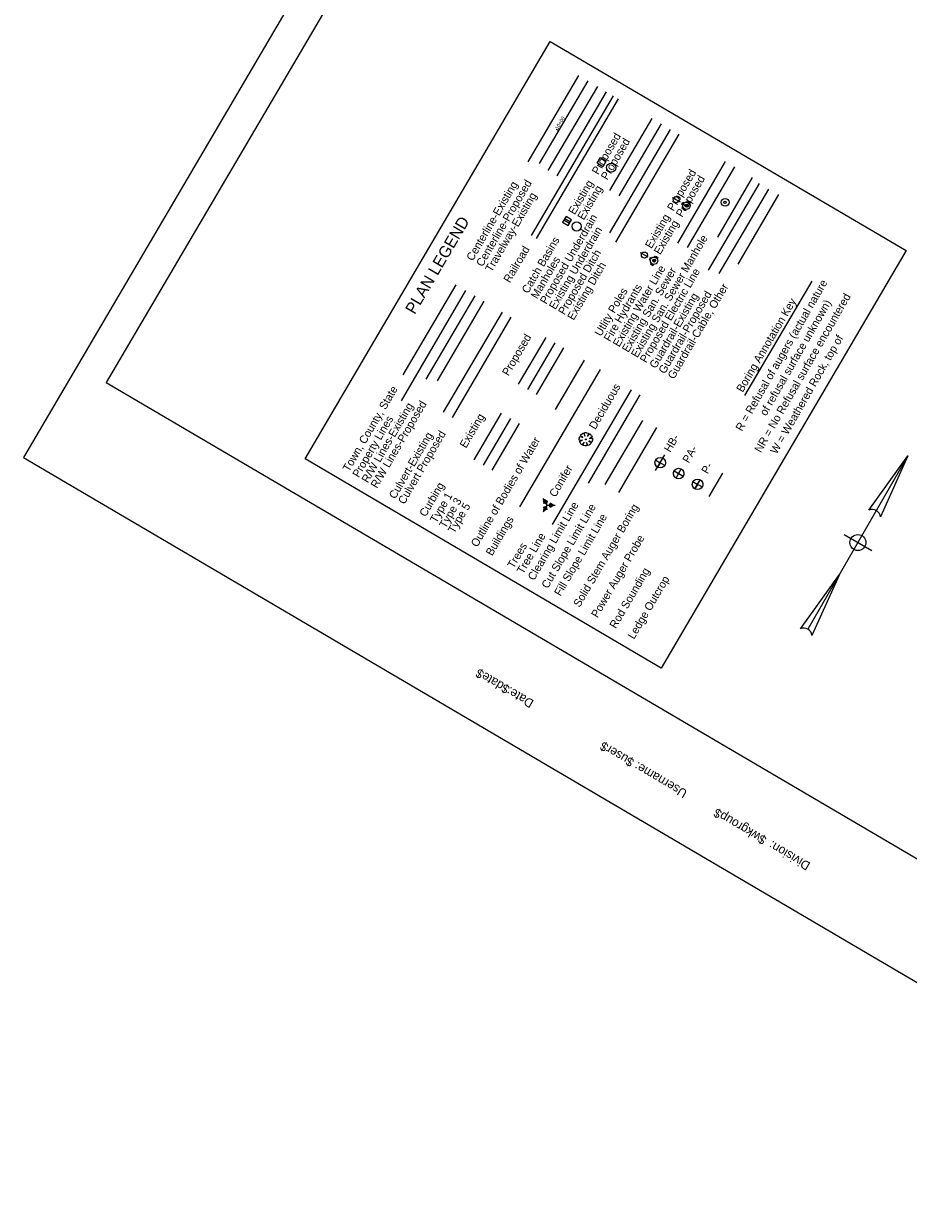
# Model space of a CAD drawing. Extents: x 423683 to 425040, y 89137 to 90655.
# Drawn here: x 423683 to 424180, y 89137 to 89799 of the extents above; entities that cross this region are included whole.
import ezdxf

# ---------------------------------------------------------------- set-up
doc = ezdxf.new("R2010")
doc.units = 0
for name, color, linetype in [('ANNOTATION', 7, 'Continuous'), ('BLDNGS_FEATS', 7, 'Continuous'), ('BORDER', 7, 'Continuous'), ('CENTERLINE', 7, 'Continuous'), ('CLOSED DRNAGE', 7, 'Continuous'), ('CRB_SDWK_RAIL', 7, 'Continuous'), ('Cross Line', 7, 'Continuous'), ('CUTFILLCLL', 7, 'Continuous'), ('Existing ROW', 7, 'Continuous'), ('H_V CONTROLS', 7, 'Continuous'), ('OPEN DRNAGE', 7, 'Continuous'), ('PCRB_PSW_PRAIL', 7, 'Continuous'), ('PDRAIN', 7, 'Continuous'), ('PLOT BOUNDARY', 7, 'Continuous'), ('PROP LINES', 7, 'Continuous'), ('PROPSD ROW LINES', 7, 'Continuous'), ('ROAD', 7, 'Continuous'), ('S_Utilities_UG_Electrical_Line', 7, 'Continuous'), ('State Seal', 7, 'Continuous'), ('TREES_BUSHES', 7, 'Continuous'), ('Truck Apron', 7, 'Continuous'), ('UTILS AERIAL', 7, 'Continuous'), ('UTILS GRND', 7, 'Continuous'), ('WATER_DAM', 7, 'Continuous')]:
    doc.layers.add(name, color=color, linetype=linetype)

msp = doc.modelspace()

# ---------------------------------------------------------------- linework, layer by layer
at = {"layer": 'ANNOTATION'}
msp.add_line((424088.38, 89590.05), (424126.1, 89654.28), dxfattribs=at)
at = {"layer": 'BLDNGS_FEATS'}
msp.add_line((423961.79, 89527.44), (424007.08, 89604.57), dxfattribs=at)
at = {"layer": 'BORDER'}
for p, q in [((424336.78, 90632.07), (423729.12, 89597.3)), ((423729.12, 89597.3), (424408.18, 89198.52))]:
    msp.add_line(p, q, dxfattribs=at)
msp.add_lwpolyline([(423840.95, 89554.31), (423978.82, 89789.08), (424179.05, 89671.49), (424041.19, 89436.72)], close=True, dxfattribs=at)
at = {"layer": 'CENTERLINE'}
for p, q in [((423966.41, 89721.34), (423994.98, 89769.99)), ((423972.8, 89720.51), (424000.09, 89766.98)), ((423983.59, 89738.88), (423982.38, 89739.6))]:
    msp.add_line(p, q, dxfattribs=at)
at = {"layer": 'CLOSED DRNAGE'}
for p, q in [((423989.6, 89686.72), (423986.47, 89688.56)), ((423987.04, 89689.53), (423990.16, 89687.69))]:
    msp.add_line(p, q, dxfattribs=at)
msp.add_lwpolyline([(424005.18, 89720.59), (424007.11, 89723.87), (424010.38, 89721.94), (424008.46, 89718.67)], close=True, dxfattribs=at)
msp.add_lwpolyline([(423985.8, 89687.42), (423988.93, 89685.59), (423990.85, 89688.86), (423987.72, 89690.69), (423985.8, 89687.42)], dxfattribs=at)
at = {"layer": 'CRB_SDWK_RAIL'}
for p, q in [((424096.32, 89709.25), (424067.65, 89660.43)), ((424107.25, 89702.97), (424084.27, 89663.82)), ((423951.27, 89580.11), (423935.89, 89553.91)), ((423956.42, 89577.08), (423941.04, 89550.89)), ((423961.34, 89574.19), (423945.95, 89548))]:
    msp.add_line(p, q, dxfattribs=at)
at = {"layer": 'Cross Line'}
msp.add_line((424009.72, 89539.89), (424030.87, 89575.91), dxfattribs=at)
at = {"layer": 'CUTFILLCLL'}
msp.add_line((424000.26, 89540.67), (424029.42, 89590.33), dxfattribs=at)
at = {"layer": 'Existing ROW'}
msp.add_line((423909.05, 89599.15), (423936.55, 89645.98), dxfattribs=at)
at = {"layer": 'H_V CONTROLS'}
for p, q in [((424038.07, 89547.76), (424043.3, 89556.66)), ((424180.03, 89556.04), (424123.78, 89458.61)), ((424158.04, 89525.44), (424180.03, 89556.04)), ((424180.03, 89556.04), (424164.53, 89521.69)), ((424048.53, 89547.63), (424053.62, 89544.64)), ((424049.58, 89543.59), (424052.57, 89548.68)), ((424068.15, 89533.21), (424075.87, 89546.36)), ((424059.15, 89541.54), (424064.24, 89538.55)), ((424060.2, 89537.5), (424063.19, 89542.59)), ((424144.11, 89511.83), (424159.7, 89502.83)), ((424119.53, 89458.74), (424141.53, 89489.34)), ((424141.53, 89489.34), (424126.02, 89454.99))]:
    msp.add_line(p, q, dxfattribs=at)
for points in [[(424040.69, 89552.21), (424039.19, 89549.66), (424038.86, 89549.9), (424038.55, 89550.18), (424038.29, 89550.5), (424038.04, 89550.9), (424037.9, 89551.25), (424037.77, 89551.77), (424037.74, 89552.12), (424037.8, 89552.8), (424037.95, 89553.31), (424038.14, 89553.7)], [(424040.69, 89552.21), (424042.18, 89554.76), (424042.52, 89554.52), (424042.83, 89554.24), (424043.09, 89553.92), (424043.34, 89553.52), (424043.48, 89553.17), (424043.61, 89552.65), (424043.64, 89552.3), (424043.58, 89551.62), (424043.43, 89551.11), (424043.24, 89550.71)], [(424051.07, 89546.14), (424049.58, 89543.59), (424049.24, 89543.83), (424048.93, 89544.11), (424048.67, 89544.43), (424048.43, 89544.83), (424048.28, 89545.17), (424048.15, 89545.7), (424048.12, 89546.05), (424048.18, 89546.73), (424048.33, 89547.24), (424048.53, 89547.63)], [(424051.07, 89546.14), (424052.57, 89548.68), (424052.91, 89548.45), (424053.21, 89548.17), (424053.47, 89547.85), (424053.72, 89547.45), (424053.86, 89547.1), (424054, 89546.57), (424054.03, 89546.23), (424053.97, 89545.55), (424053.81, 89545.04), (424053.62, 89544.64)], [(424061.7, 89540.04), (424060.2, 89537.5), (424059.86, 89537.73), (424059.56, 89538.01), (424059.3, 89538.33), (424059.05, 89538.73), (424058.91, 89539.08), (424058.77, 89539.61), (424058.74, 89539.95), (424058.8, 89540.63), (424058.96, 89541.14), (424059.15, 89541.54)], [(424061.7, 89540.04), (424063.19, 89542.59), (424063.53, 89542.35), (424063.84, 89542.07), (424064.1, 89541.75), (424064.34, 89541.35), (424064.49, 89541.01), (424064.62, 89540.48), (424064.65, 89540.13), (424064.59, 89539.45), (424064.44, 89538.94), (424064.24, 89538.55)]]:
    msp.add_lwpolyline(points, close=True, dxfattribs=at)
for centre, radius in [((424040.69, 89552.21), 2.95), ((424051.07, 89546.14), 2.95), ((424061.7, 89540.04), 2.95), ((424151.91, 89507.33), 4.5)]:
    msp.add_circle(centre, radius, dxfattribs=at)
for centre in [(424160.04, 89521.41), (424121.53, 89454.71)]:
    msp.add_arc(centre, 4.5, 3.55731, 116.44269, dxfattribs=at)
at = {"layer": 'OPEN DRNAGE'}
for p, q in [((424015.68, 89676.33), (424051.27, 89736.93)), ((423918.85, 89580.62), (423951.93, 89636.95))]:
    msp.add_line(p, q, dxfattribs=at)
at = {"layer": 'PCRB_PSW_PRAIL'}
for p, q in [((424073.83, 89658.63), (424101.72, 89706.13)), ((423976.26, 89622.66), (423960.88, 89596.47)), ((423981.41, 89619.64), (423966.03, 89593.44)), ((423986.33, 89616.75), (423970.95, 89590.56))]:
    msp.add_line(p, q, dxfattribs=at)
at = {"layer": 'PDRAIN'}
for p, q in [((424012.43, 89705.28), (424036.21, 89745.77)), ((424012.41, 89681.54), (424046.56, 89739.69)), ((424017.56, 89702.27), (424041.34, 89742.76)), ((423923.85, 89577.68), (423956.93, 89634.01))]:
    msp.add_line(p, q, dxfattribs=at)
at = {"layer": 'PLOT BOUNDARY'}
msp.add_lwpolyline([(424393.97, 89137.31), (425039.61, 90236.75), (424328.2, 90654.52), (423682.56, 89555.08)], close=True, dxfattribs=at)
at = {"layer": 'PROP LINES'}
for p, q in [((423896.17, 89601.54), (423925.93, 89652.22)), ((423895.08, 89587.1), (423931.42, 89648.99))]:
    msp.add_line(p, q, dxfattribs=at)
at = {"layer": 'PROPSD ROW LINES'}
msp.add_line((423915.46, 89598.32), (423941.68, 89642.97), dxfattribs=at)
at = {"layer": 'ROAD'}
for p, q in [((423977.75, 89716.51), (424005.52, 89763.8)), ((423982.75, 89713.57), (424010.52, 89760.86))]:
    msp.add_line(p, q, dxfattribs=at)
at = {"layer": 'S_Utilities_UG_Electrical_Line'}
msp.add_line((424073.02, 89679.11), (424092.69, 89712.61), dxfattribs=at)
at = {"layer": 'State Seal'}
msp.add_line((424056.74, 89698.93), (424056.83, 89699.08), dxfattribs=at)
at = {"layer": 'TREES_BUSHES'}
for p, q in [((423980.01, 89517.47), (424024.5, 89593.23)), ((423977.09, 89528.28), (423974.85, 89524.47)), ((423976.64, 89527.52), (423974.87, 89527.1)), ((423976.2, 89526.76), (423974.87, 89526.44)), ((423976.22, 89529.82), (423974.89, 89530.16)), ((423976.66, 89529.05), (423974.89, 89529.51)), ((423975.78, 89530.59), (423974.9, 89530.82)), ((423977.09, 89528.28), (423974.91, 89532.13)), ((423975.35, 89531.36), (423974.91, 89531.47)), ((423975.47, 89531.8), (423975.35, 89531.36)), ((423976.04, 89531.47), (423975.78, 89530.59)), ((423976.56, 89525.45), (423976.2, 89526.76)), ((423976.61, 89531.13), (423976.22, 89529.82)), ((423977.13, 89525.77), (423976.64, 89527.52)), ((423977.17, 89530.8), (423976.66, 89529.05)), ((423977.09, 89528.28), (423981.51, 89528.25)), ((423979.25, 89529.58), (423977.98, 89528.28)), ((423979.23, 89526.96), (423977.98, 89528.28)), ((423979.81, 89529.25), (423978.86, 89528.27)), ((423979.8, 89527.28), (423978.86, 89528.27)), ((423980.38, 89528.92), (423979.74, 89528.26)), ((423980.37, 89527.61), (423979.74, 89528.26)), ((423980.94, 89528.59), (423980.63, 89528.26)), ((423980.94, 89527.93), (423980.63, 89528.26)), ((423975.75, 89526), (423974.86, 89525.79)), ((423975.3, 89525.24), (423974.86, 89525.13)), ((423975.42, 89524.8), (423975.3, 89525.24)), ((423975.99, 89525.12), (423975.75, 89526))]:
    msp.add_line(p, q, dxfattribs=at)
msp.add_lwpolyline([(423997.89, 89563.77), (423997.33, 89562.97), (423996.62, 89562.35), (423995.9, 89563.04), (423996.01, 89563.23), (423995.71, 89563.32), (423995.3, 89564.08), (423996, 89564.54), (423996.99, 89564.91), (423995.94, 89564.74), (423995.11, 89564.8), (423995.1, 89565.67), (423995.32, 89565.89), (423995.13, 89566), (423995.42, 89566.95), (423996.35, 89566.76), (423997.22, 89566.33), (423996.42, 89566.89), (423995.8, 89567.6), (423996.49, 89568.32), (423996.68, 89568.21), (423996.77, 89568.51), (423997.53, 89568.92), (423997.99, 89568.22), (423998.36, 89567.23), (423998.19, 89568.28), (423998.25, 89569.11), (423999.12, 89569.12), (423999.34, 89568.9), (423999.45, 89569.09), (424000.41, 89568.8), (424000.21, 89567.87), (423999.78, 89567), (424000.34, 89567.8), (424001.05, 89568.42), (424001.77, 89567.73), (424001.66, 89567.54), (424001.96, 89567.45), (424002.37, 89566.69), (424001.67, 89566.23), (424000.68, 89565.86), (424001.73, 89566.03), (424002.56, 89565.97), (424002.57, 89565.1), (424002.35, 89564.88), (424002.55, 89564.77), (424002.25, 89563.81), (424001.32, 89564.01), (424000.45, 89564.44), (424001.25, 89563.88), (424001.87, 89563.17), (424001.18, 89562.45), (424000.99, 89562.56), (424000.9, 89562.26), (424000.14, 89561.85), (423999.68, 89562.55), (423999.31, 89563.54), (423999.48, 89562.49), (423999.42, 89561.66), (423998.55, 89561.65), (423998.33, 89561.87), (423998.22, 89561.67), (423997.27, 89561.97), (423997.46, 89562.9), (423997.89, 89563.77)], dxfattribs=at)
msp.add_circle((423998.84, 89565.32), 0.234, dxfattribs=at)
at = {"layer": 'Truck Apron'}
msp.add_line((424017.41, 89535.51), (424038.81, 89571.95), dxfattribs=at)
at = {"layer": 'UTILS AERIAL'}
for p, q in [((424047.44, 89701.43), (424051.83, 89698.85)), ((424048.18, 89700.99), (424051.08, 89699.29)), ((424033.98, 89667.71), (424029.6, 89670.28))]:
    msp.add_line(p, q, dxfattribs=at)
for centre, radius in [((424049.63, 89700.14), 1.69), ((424031.78, 89669), 1.68)]:
    msp.add_circle(centre, radius, dxfattribs=at)
at = {"layer": 'UTILS GRND'}
for p, q in [((423968.24, 89680.07), (424014.36, 89758.6)), ((423971.11, 89678.38), (424017.23, 89756.92)), ((424050.54, 89675.68), (424077.48, 89721.54)), ((424056.05, 89673.32), (424082.6, 89718.53)), ((424053.17, 89698.07), (424053.02, 89698.16)), ((424054.03, 89694.32), (424054.13, 89694.49)), ((424034.96, 89667.13), (424034.81, 89667.22)), ((424038.53, 89667.99), (424038.62, 89668.14)), ((424035.82, 89663.38), (424035.92, 89663.55))]:
    msp.add_line(p, q, dxfattribs=at)
for points in [[(424053.36, 89697), (424052.8, 89697.33), (424053.64, 89698.76), (424054.2, 89698.43)], [(424055.72, 89698.77), (424056.05, 89699.34), (424057.47, 89698.5), (424057.14, 89697.94)], [(424053.74, 89695.51), (424053.41, 89694.95), (424054.83, 89694.11), (424055.16, 89694.68)], [(424035.15, 89666.06), (424034.59, 89666.39), (424035.43, 89667.82), (424035.99, 89667.49)], [(424037.51, 89667.84), (424037.84, 89668.4), (424039.26, 89667.57), (424038.93, 89667)], [(424035.53, 89664.58), (424035.2, 89664.01), (424036.62, 89663.18), (424036.95, 89663.74)]]:
    msp.add_lwpolyline(points, dxfattribs=at)
for points in [[(424056.6, 89699.01), (424056.69, 89699.16), (424056.98, 89699), (424056.89, 89698.84)], [(424053.15, 89697.92), (424053.29, 89698.17), (424053.09, 89698.29), (424052.94, 89698.04)], [(424054.03, 89694.58), (424053.92, 89694.38), (424054.15, 89694.25), (424054.27, 89694.44)], [(424034.94, 89666.98), (424035.08, 89667.23), (424034.88, 89667.35), (424034.73, 89667.1)], [(424038.39, 89668.07), (424038.48, 89668.22), (424038.77, 89668.06), (424038.68, 89667.91)], [(424035.82, 89663.64), (424035.71, 89663.45), (424035.94, 89663.31), (424036.06, 89663.51)]]:
    msp.add_lwpolyline(points, close=True, dxfattribs=at)
for centre, radius in [((424013.12, 89718.14), 2.6), ((424077.23, 89698.66), 2.16), ((424077.21, 89698.64), 0.664), ((423993.71, 89685.08), 2.6)]:
    msp.add_circle(centre, radius, dxfattribs=at)
for centre, major_axis in [((424055.45, 89696.73), (1.05, 1.79)), ((424055.45, 89696.73), (0.415, 0.707)), ((424055.45, 89696.73), (0.204, 0.347)), ((424037.24, 89665.8), (1.05, 1.79)), ((424037.24, 89665.8), (0.415, 0.707)), ((424037.24, 89665.8), (0.204, 0.347))]:
    msp.add_ellipse(centre, major_axis=major_axis, ratio=0.992647, dxfattribs=at)
at = {"layer": 'WATER_DAM'}
msp.add_line((423981.82, 89582.19), (423998.07, 89609.86), dxfattribs=at)

# ---------------------------------------------------------------- texts
at = {"layer": 'ANNOTATION'}
for s, height, p in [('10+00', 2.025, (423983.19, 89739.45)), ('Existing   Proposed', 4.5, (423992.58, 89691.33)), ('Existing   Proposed', 4.5, (423997.7, 89688.32)), ('Centerline-Proposed', 4.5, (423940.72, 89662.06)), ('Existing  Proposed', 4.5, (424035.76, 89672.27)), ('Existing  Proposed', 4.5, (424040.69, 89668.83)), ('Centerline-Existing', 4.5, (423935.22, 89665.29)), ('Travelway-Existing', 4.5, (423945.85, 89659.05)), ('PLAN LEGEND', 6.5625, (423902.58, 89635.2)), ('Proposed Underdrain', 4.5, (423976.6, 89640.99)), ('Catch Basins', 4.5, (423966.35, 89647.01)), ('Existing Underdrain', 4.5, (423981.73, 89637.98)), ('Existing San. Sewer Manhole', 4.5, (424027.85, 89610.89)), ('Railroad', 4.5, (423956.1, 89653.03)), ('Manholes', 4.5, (423971.48, 89644)), ('Proposed Ditch', 4.5, (423986.85, 89634.97)), ('Existing Ditch', 4.5, (423991.98, 89631.96)), ('Existing Water Line', 4.5, (424017.6, 89616.91)), ('Existing San. Sewer', 4.5, (424022.73, 89613.9)), ('Proposed Electric Line', 4.5, (424032.81, 89607.98)), ('Fire Hydrants', 4.5, (424012.48, 89619.92)), ('Guardrail-Cable, Other', 4.5, (424048.42, 89598.81)), ('Utlity Poles', 4.5, (424007.35, 89622.93)), ('Guardrail-Existing', 4.5, (424038.17, 89604.83)), ('Guardrail-Proposed', 4.5, (424043.29, 89601.82)), ('Boring Annotation Key', 4.5, (424087.09, 89591.44)), ('Proposed', 4.5, (423955.33, 89600.68)), ('Town, County, State', 4.5, (423865.64, 89546.72)), ('Deciduous', 4.5, (424004.19, 89570.53)), ('R/W Lines-Proposed', 4.5, (423881.39, 89537.47)), ('R/W Lines-Existing', 4.5, (423876.27, 89540.48)), ('Existing', 4.5, (423931.46, 89560.03)), ('Property Lines', 4.5, (423871.14, 89543.49)), ('Culvert-Existing', 4.5, (423891.64, 89531.45)), ('Culvert Proposed', 4.5, (423896.77, 89528.44)), ('Outline of Bodies of Water', 4.5, (423937.77, 89504.37)), ('Conifer', 4.5, (423981.82, 89532.43)), ('Curbing', 4.5, (423908.77, 89521.4)), ('Type 1', 4.5, (423914.74, 89517.89)), ('Type 3', 4.5, (423919.93, 89514.94)), ('Type 5', 4.5, (423924.85, 89512.06)), ('Clearing Limit Line', 4.5, (423969.74, 89485.59)), ('Cut Slope Limit Line', 4.5, (423977.48, 89481.05)), ('Solid Stem Auger Boring', 4.5, (423995.37, 89470.54)), ('Buildings', 4.5, (423946.13, 89499.45)), ('Fill Slope Limit Line', 4.5, (423984.61, 89476.86)), ('Trees', 4.5, (423958.27, 89492.33)), ('Tree Line', 4.5, (423963.59, 89489.2)), ('Power Auger Probe', 4.5, (424005.44, 89464.63)), ('Rod Sounding', 4.5, (424015.72, 89458.59)), ('Ledge Outcrop', 4.5, (424025.95, 89452.58))]:
    msp.add_text(s, height=height, rotation=59.57663, dxfattribs=at).set_placement(p)
at = {"layer": 'BORDER'}
for s, p in [('$date$', (423956.51, 89426.23)), ('Date:', (423970.02, 89418.3)), ('$user$', (424026.45, 89385.16)), ('Username:', (424056.35, 89367.6)), ('$wkgroup$', (424100.96, 89341.41)), ('Division:', (424125.56, 89326.96))]:
    msp.add_text(s, height=5.022, rotation=149.57663, dxfattribs=at).set_placement(p)
at = {"layer": 'H_V CONTROLS'}
for s, height, rotation, p in [('R = Refusal of augers (actual nature', 4.5, 60.11949, (424086.68, 89569.56)), ('NR = No Refusal surface encountered', 4.5, 60.11949, (424097.31, 89557.5)), ('of refusal surface unknown)', 4.5, 60.11949, (424100.26, 89578.16)), ('W = Weathered Rock, top of', 4.5, 60.15058, (424106.19, 89556.66)), ('HB-', 4.429, 59.57663, (424046.35, 89557.71)), ('PA-', 4.429, 59.57663, (424056.73, 89551.64)), ('P-', 4.429, 59.57663, (424067.36, 89545.54))]:
    msp.add_text(s, height=height, rotation=rotation, dxfattribs=at).set_placement(p)

doc.saveas('drawing.dxf')
